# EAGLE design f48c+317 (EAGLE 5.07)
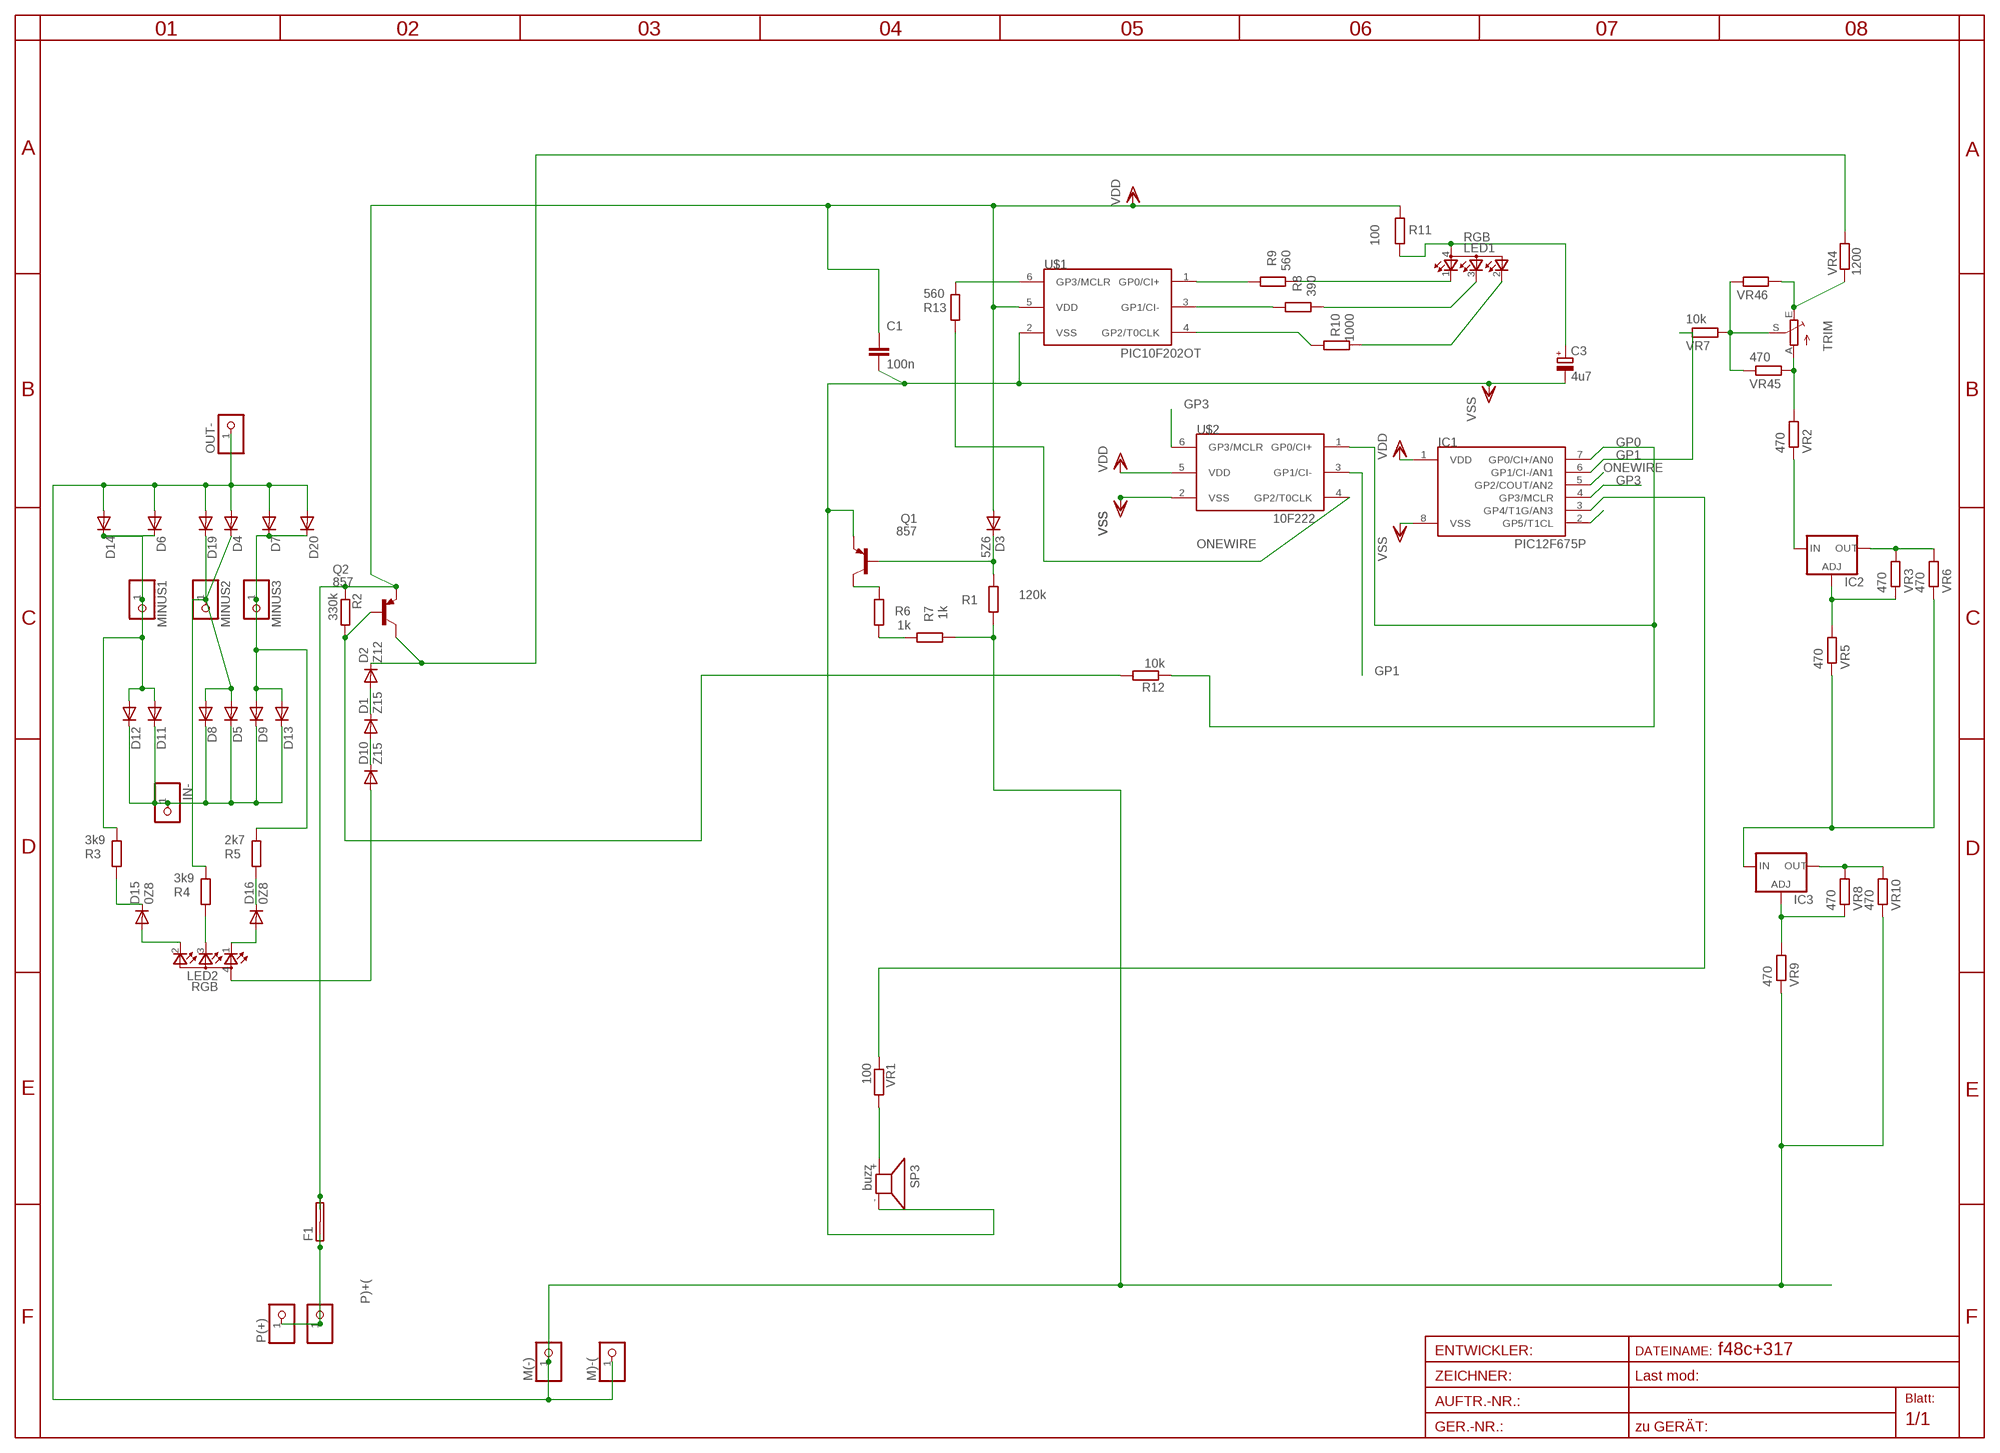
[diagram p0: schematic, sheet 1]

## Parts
C1  100n  C-EUC1206  [C1206]
C3  4u7  CPOL-EUSMCA  [SMC_A]
D1  Z15  DIODE-MINIMELF  [MINIMELF]
D2  Z12  DIODE-MINIMELF  [MINIMELF]
D3  5Z6  DIODE-MINIMELF  [MINIMELF]
D4  DIODE-SMC  [SMC]
D5  DIODE-SMC  [SMC]
D6  DIODE-SMC  [SMC]
D7  DIODE-SMC  [SMC]
D8  DIODE-SMC  [SMC]
D9  DIODE-SMC  [SMC]
D10  Z15  DIODE-MINIMELF  [MINIMELF]
D11  DIODE-SMC  [SMC]
D12  DIODE-SMC  [SMC]
D13  DIODE-SMC  [SMC]
D14  DIODE-SMC  [SMC]
D15  0Z8  DIODE-MINIMELF  [MINIMELF]
D16  0Z8  DIODE-MINIMELF  [MINIMELF]
D19  DIODE-SMC  [SMC]
D20  DIODE-SMC  [SMC]
F1  SHK20L7MM5  [7MM5]
IC1  PIC12F675P  [DIL8]
IC2  LM317LM-OUTPIN7  [SO08]
IC3  LM317LM-OUTPIN7  [SO08]
IN-  PINHD-1X12MM3  [1X2MM3]
LED1  RGB  GM1WA55311A  [FULL3528]
LED2  RGB  GM1WA55311A  [FULL3528]
M(-)  PINHD-1X14.5MM  [1X4MM5]
M)-(  PINHD-1X11X0.4  [1X01]
MINUS1  PINHD-1X12MM3  [1X2MM3]
MINUS2  PINHD-1X12MM3  [1X2MM3]
MINUS3  PINHD-1X12MM3  [1X2MM3]
OUT-  PINHD-1X12MM3  [1X2MM3]
P(+)  PINHD-1X14.5MM  [1X4MM5]
P)+(  PINHD-1X11X0.4  [1X01]
Q1  857  BC857ALT1SMD  [SOT23-BEC]
Q2  857  BC857ALT1SMD  [SOT23-BEC]
R1  120k  R-EU_R1206  [R1206]
R2  330k  R-EU_R0805  [R0805]
R3  3k9  R-EU_0207/20  [0207/20]
R4  3k9  R-EU_0207/20  [0207/20]
R5  2k7  R-EU_0207/22  [0207/22]
R6  1k  R-EU_R1206  [R1206]
R7  1k  R-EU_R1206  [R1206]
R8  390  R-EU_R0805  [R0805]
R9  560  R-EU_R0805  [R0805]
R10  1000  R-EU_R0805  [R0805]
R11  100  R-EU_R1206  [R1206]
R12  10k  R-EU_R1206  [R1206]
R13  560  R-EU_R0805  [R0805]
SP3  buzz  KSS12017MM  [KSS1202]
TRIM  TRIM_EU-S64W  [S64W]
U$1  PIC10F202OT  [SOT23-6]
U$2  10F222  PIC10F204OT  [SOT23-6]
VR1  100  R-EU_R0805  [R0805]
VR2  470  R-EU_R0805  [R0805]
VR3  470  R-EU_R0805  [R0805]
VR4  1200  R-EU_R0805  [R0805]
VR5  470  R-EU_R0805  [R0805]
VR6  470  R-EU_R0805  [R0805]
VR7  10k  R-EU_R0805  [R0805]
VR8  470  R-EU_R0805  [R0805]
VR9  470  R-EU_R0805  [R0805]
VR10  470  R-EU_R0805  [R0805]
VR45  470  R-EU_R0805  [R0805]
VR46  470  R-EU_R0805  [R0805]

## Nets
A: C3.+ LED1.4(A) R11.1
B: LED1.3(CBLUE) R8.1
B1: D6.C D11.A D12.A D14.C MINUS1.1 R3.1
B2: D7.C D9.A D13.A D20.C MINUS3.1 R5.1
B3: D4.C D5.A D8.A D19.C MINUS2.1 R4.1
BUZZ+: SP3.+ VR1.2
G: LED1.2(CGREEN) R10.1
GP0: IC1.7(GP0/CI+/AN0) R12.1 U$2.1(GP0/CI+)
GP0C: R9.2 U$1.1(GP0/CI+)
GP1: IC1.6(GP1/CI-/AN1) U$2.3(GP1/CI-) VR7.1
GP1C: R8.2 U$1.3(GP1/CI-)
GP2C: R10.2 U$1.4(GP2/T0CLK)
GP3: IC1.4(GP3/MCLR) U$2.6(GP3/MCLR)
GP3_2: R13.1 U$1.6(GP3/MCLR)
IN+: F1.1A F1.1B P(+).1 P)+(.1
IN-: D5.C D8.C D9.C D11.C D12.C D13.C IN-.1
IOBEEP: IC1.3(GP4/T1G/AN3) VR1.1
N$1: D1.C D2.A
N$2: D3.C Q1.B R1.1
N$4: D1.A D10.C
N$5: IC2.7(OUT) VR3.2 VR6.2
N$6: Q1.C R6.2
N$7: TRIM.A VR2.2 VR45.2
N$8: IC2.1(IN) VR2.1
N$9: D16.A LED2.1(CRED)
N$10: D10.A LED2.4(A)
N$11: IC2.4(ADJ) VR3.1 VR5.2
N$13: D15.C R3.2
N$14: IC3.1(IN) VR5.1 VR6.1
N$15: D15.A LED2.2(CGREEN)
N$16: LED2.3(CBLUE) R4.2
N$18: R6.1 R7.2
N$19: D16.C R5.2
N$20: Q2.B R2.2 R12.2
N$21: IC3.4(ADJ) VR8.1 VR9.2
N$22: TRIM.S VR7.2 VR45.1 VR46.1
N$24: TRIM.E VR4.1 VR46.2
N$25: D2.C Q2.C VR4.2
N$26: IC3.7(OUT) VR8.2 VR10.2
N$38: IC1.2(GP5/T1CL)
ONEWIRE: IC1.5(GP2/COUT/AN2) R13.2 U$2.4(GP2/T0CLK)
OUT-: D4.A D6.A D7.A D14.A D19.A D20.A M(-).1 M)-(.1 OUT-.1 R1.2 R7.1 VR9.1 VR10.1
R: LED1.1(CRED) R9.1
VDD: C1.1 D3.A F1.2A F1.2B IC1.1(VDD) Q2.E R2.1 R11.2 U$1.5(VDD) U$2.5(VDD)
VSS: C1.2 C3.- IC1.8(VSS) Q1.E SP3.- U$1.2(VSS) U$2.2(VSS)

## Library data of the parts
C1 = rcl:C-EU: CAPACITOR, European symbol
C3 = rcl:CPOL-EU: POLARIZED CAPACITOR, European symbol
D1-D16 D19 D20 = diode:DIODE-: DIODE
F1 = fuse:SHK20L: FUSE HOLDER 5 x 20 mm, SH contact, SHH1 Schukat, E1073 Buerklin
IC1 = microchip-3:PIC12F6*: uPC nW 1k Program Flash memory 2x Timer Comparator 10b A/D converter/ 4xIN
IC2 IC3 = v-reg-3:LM317L: Adjustable Voltage Regulator, 1.2V to 37V, 100mA
IN- M(-) M)-( MINUS1-MINUS3 OUT- P(+) P)+( = pinhead:PINHD-1X1: PIN HEADER
LED1 LED2 = led:GM1WA55311A: Chip LED RGB Source: http://document.sharpsma.com/files/GM1WA55311A_SS.pdf
Q1 Q2 = transistor-pnp:BC857*: PNP Transistror
R1-R13 VR1-VR10 VR45 VR46 = rcl-2:R-EU_: RESISTOR, European symbol
SP3 = buzzer:KSS1201: SPEAKER
TRIM = pot:TRIM_EU-: POTENTIOMETER
U$1 U$2 = microchip-3:PIC10F2*: uPC nW 0,25/0,5k Program Flash memory Comparator

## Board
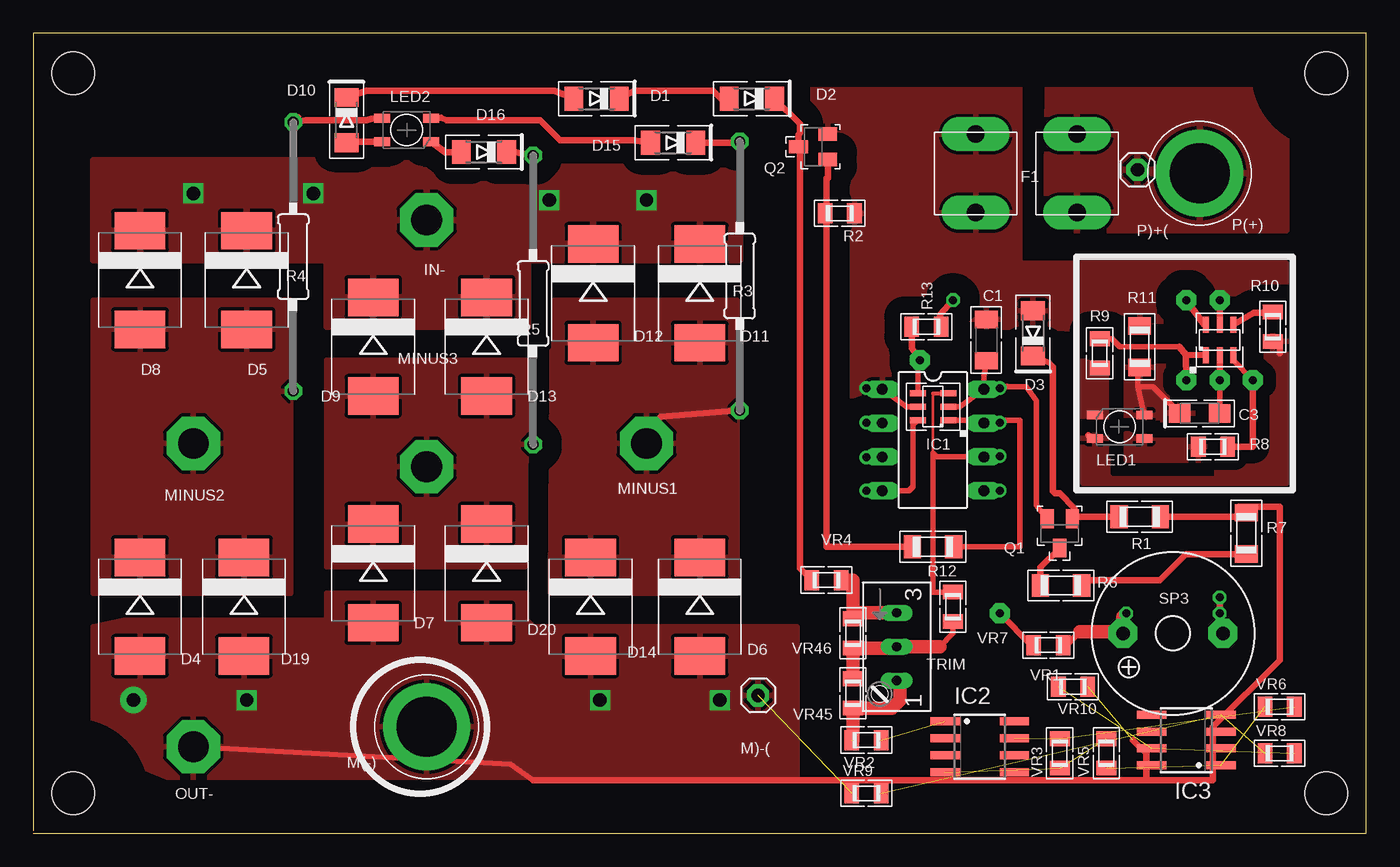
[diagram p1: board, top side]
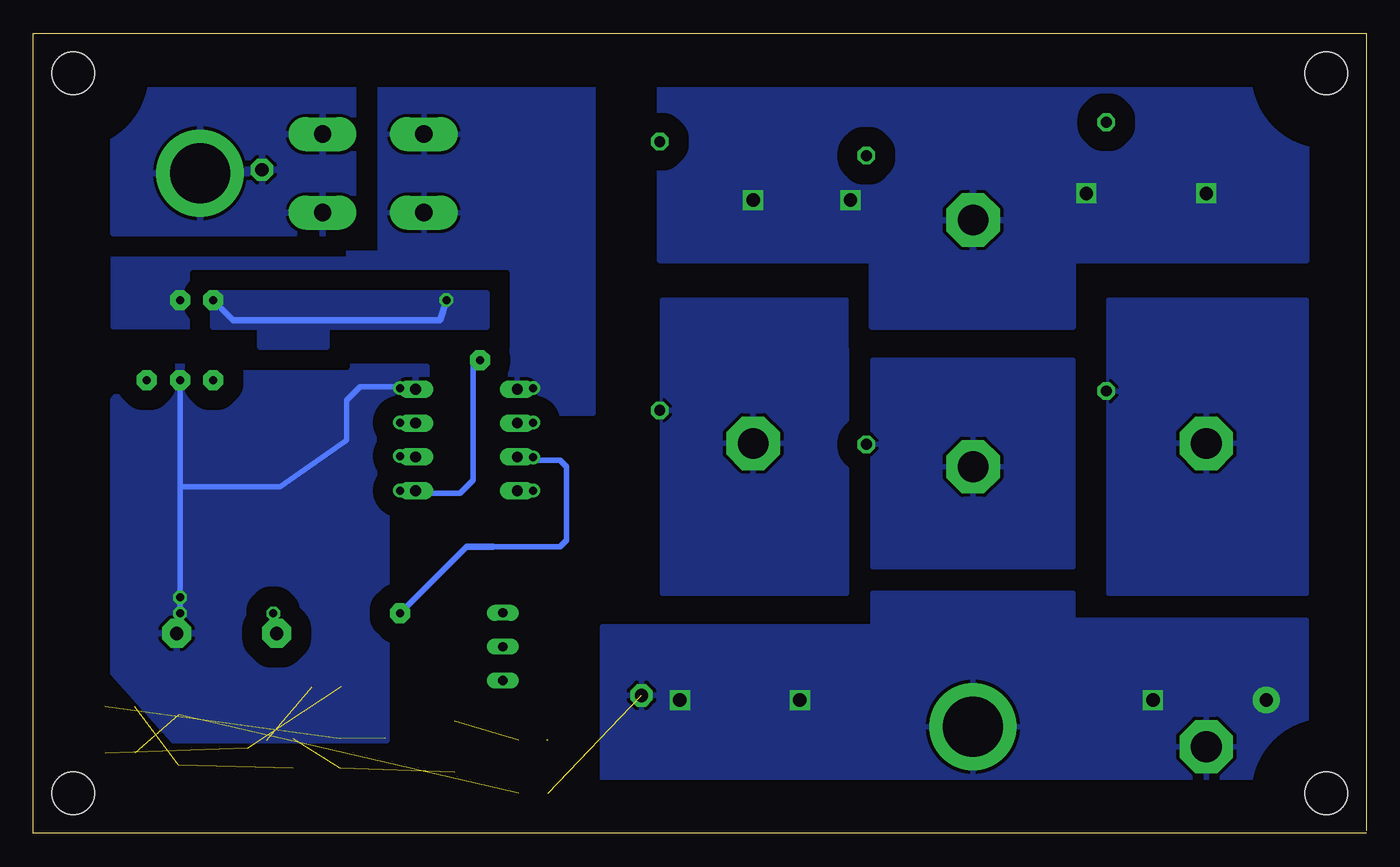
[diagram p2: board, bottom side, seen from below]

Size 100 x 60 mm. Coordinates in mm from the lower left corner, seen from the top.
Outline: 0,0 100,0 100,60 0,60 0,0.2
Copper layers (1*16): Top 0.035mm / dielectric 1.5mm / Bottom 0.035mm
Design rules "default *": minimum track width 8mil, minimum drill 4mil, track to track 8mil, track to pad 8mil, pad to pad 8mil, via to via 8mil, smd to smd 8mil, copper to edge 4mm, drill to drill 8mil, minimum pad ring 10mil, minimum via ring 8mil, stop-mask expansion 4mil, vias tented up to drill 0mil, thermal gap 10mil
Holes 3.2 mm at 3,57 3,3 97,57 97,3

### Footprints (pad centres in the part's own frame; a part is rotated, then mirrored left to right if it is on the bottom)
C1206 = smd 1.3 x 1.7: 1 -1.55,0; 2 1.55,0
SMC_A = smd 1.6 x 1.4: + -1.5,0; - 1.5,0
MINIMELF = smd 1.4 x 1.8: A 1.7,0; C -1.7,0
SMC = smd 2.8 x 3.8: A 3.7,0; C -3.7,0
7MM5 = drill 1.3 pad 2.54 long: 1A -3.8,2.94; 1B -3.8,-2.94; 2A 3.8,2.94; 2B 3.8,-2.94
DIL8 = drill 0.813 long: 1 -3.81,-3.81; 2 -1.27,-3.81; 3 1.27,-3.81; 4 3.81,-3.81; 5 3.81,3.81; 6 1.27,3.81; 7 -1.27,3.81; 8 -3.81,3.81
SO08 = smd 0.6 x 2.2: 1 -1.905,-2.6; 2 -0.635,-2.6; 3 0.635,-2.6; 4 1.905,-2.6; 5 1.905,2.6; 6 0.635,2.6; 7 -0.635,2.6; 8 -1.905,2.6
1X2MM3 = drill 2.3 pad 4 octagon: 1 0,0
FULL3528 = smd 0.65 x 1.2: 1 0.875,1.85; 2 -0.875,1.85; 3 -0.875,-1.85; 4 0.875,-1.85
1X4MM5 = drill 4.5 pad 6.35 round: 1 0,0
1X01 = drill 1 pad 1.676 octagon: 1 0,0
SOT23-BEC = smd 1 x 1.4: B -0.95,-1.1; C 0,1.1; E 0.95,-1.1
R1206 = smd 1.3 x 1.7: 1 -1.55,0; 2 1.55,0
R0805 = smd 1.1 x 1.5: 1 -1.1,0; 2 1.1,0
0207/20 = drill 0.813 octagon: 1 -10.08,0; 2 10.08,0
0207/22 = drill 0.813 octagon: 1 -10.58,0; 2 11.08,0
KSS1202 = drill 1 pad 2.159 octagon: + 3.75,0; - -3.75,0
S64W = drill 0.7 long: A 2.54,1.27; E -2.54,1.27; S 0,1.27
SOT23-6 = smd 0.45 x 1.2: 1 -1.016,-1.15; 2 0,-1.15; 3 1.016,-1.15; 4 1.016,1.15; 5 0,1.15; 6 -1.016,1.15

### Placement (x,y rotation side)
C1  71.5,37 270 top
C3  87.5,31.5 0 top
D1  42.25,55.1 180 top
D2  53.9,55.1 180 top
D3  75,37.5 90 top
D4  8,17 270 top
D5  16,41.5 270 top
D6  50,17 270 top
D7  25.5,19.5 270 top
D8  8,41.5 270 top
D9  25.5,36.5 270 top
D10  23.5,53.5 270 top
D11  50,40.5 270 top
D12  42,40.5 270 top
D13  34,36.5 270 top
D14  41.8,17 270 top
D15  48,51.8 180 top
D16  33.8,51.1 180 top
D19  15.8,17 270 top
D20  34,19.5 270 top
F1  74.5,49.5 180 top
IC1  67.5,29.5 270 top
IC2  71,6.5 270 top
IC3  86.5,7 90 top
IN-  29.5,46 180 top
LED1  81.5,30.5 90 top
LED2  28,52.75 270 top
M(-)  29.5,8 0 top
M)-(  54.37,10.35 0 top
MINUS1  46,29.25 180 top
MINUS2  12,29.25 180 top
MINUS3  29.5,27.5 180 top
OUT-  12,6.5 180 top
P(+)  87.5,49.5 0 top
P)+(  82.84,49.77 0 top
Q1  77,22.5 180 top
Q2  58.5,51.5 90 top
R1  83,23.75 0 top
R2  60.5,46.5 180 top
R3  53,41.8 90 top
R4  19.5,43.25 90 top
R5  37.5,39.75 90 top
R6  77.1,18.6 180 top
R7  91,22.5 270 top
R8  88.5,29 0 top
R9  80,36 90 top
R10  93,38 90 top
R11  83,36.5 90 top
R12  67.5,21.5 180 top
R13  67,38 180 top
SP3  85.5,15 180 top
TRIM  63.5,14 270 top
U$1  89,37 0 top
U$2  67.5,32 90 top
VR1  76.16,14.11 0 top
VR2  62.5,7 180 top
VR3  77,6 90 top
VR4  59.5,19 180 top
VR5  80.5,6 90 top
VR6  93.5,9.5 0 top
VR7  69,17 270 top
VR8  93.5,6 0 top
VR9  62.5,3 0 top
VR10  78,11 180 top
VR45  61.5,10.5 270 top
VR46  61.5,15 90 top

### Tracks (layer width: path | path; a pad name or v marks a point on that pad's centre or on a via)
A
  Top 0.4: 82.85,33.5 82.85,34.8 R11.1 | LED1.4 82.85,33.5 | C3.+ 84,33.5 82.85,33.5
  pour Top (isolate 1, rank 2): 82,35.5 87,35.5 87,31 82,31
B
  pour Top (isolate 1.016): 82,30 83.5,30 84,29.5 88,29.5 88,28 82,28
B1
  Top 0.5: R3.1 47.05,31.25 MINUS1.1
  pour Top (isolate 1.5, rank 4): 52.8,18 38.8,18 38.8,40 52.8,40
  pour Bottom (isolate 1.5, rank 4): 52.8,18 39,18 39,40 52.8,40
B2
  pour Top (isolate 1.5, rank 3): 22,20 22,35.5 37,35.5 36.9,20
  pour Bottom (isolate 1.5, rank 3): 22,20 22,35.5 37,35.5 37,20
B3
  pour Top (isolate 1.5, rank 4): 4.5,18 4.5,40 19.3,40 19.3,18
  pour Bottom (isolate 1.5, rank 4): 4.5,18 4.5,40 19.3,40 19.3,18
BUZZ+  (via drill 0.6)
  Top 0.406: 81.75,16.25 v82,16.5 81.39,15.11
  Top 0.5: VR1.2 77.5,14.11 78.5,15.11
  Top 1: 81.75,16.25 SP3.+ | 78.5,15.11 81.39,15.11
G
  Top 0.5: LED1.2 79.15,29.85 79.5,29.5 | R10.1 93.5,36.9 93.5,36
  pour Top (isolate 1, rank 2): 78.75,30 80.5,30 80.5,28 92.5,28 92.5,37.5 94,37.5 94,26.25 78.75,26.25
GP0  (via drill 0.6 pad 1)
  Top 0.4: U$2.1 71.1,30.98 IC1.7
  Top 0.406: R12.1 74,21.5 74,31 71.5,31 71.31,30.81 IC1.7 71.34,30.8 v72.5,30.8
GP0C  (via drill 0.6 pad 1.5)
  Top 0.4: R9.2 80.9,37.1 81.5,36.5 85.97,36.5
  Top 0.5: 86.48,35.88 U$1.1 | 86.48,35.88 v86.5,34 | 85.97,36.5 86.48,35.88
GP1  (via drill 0.6 pad 1)
  Top 0.2: 67.5,28.5 67.5,33
  Top 0.3: 67.5,33 68.63,33
  Top 0.4: IC1.6 67.77,28.23 67.5,28.5 67.5,18.1
  Top 0.406: 67.5,18.1 VR7.1 | IC1.6 72.43,28.23 v72.5,28.3 | 68.63,33 U$2.3
GP1C  (via drill 0.6 pad 1.5)
  Top 0.4: U$1.3 90.02,35.48 v91.5,34
  Top 0.5: v91.5,34 91.5,29 R8.2
GP2C
  Top 0.5: U$1.4 91.55,39.05 93,39.05 R10.2
GP3  (via drill 0.6 pad 1)
  Top 0.4: IC1.4 65.69,25.69 66,26 66,30.63 U$2.6
  Top 0.406: IC1.4 v62.51,25.69 v62.5,25.7
GP3_2  (via drill 0.6 pad 1, 0.6 pad 1.5)
  Top 0.5: U$1.6 87.85,38.15 v86.5,40 | v69,40 68,38.9 R13.1
  Bottom 0.5: v86.5,40 85,38.5 69.5,38.5 v69,40
  pour Bottom (isolate 1): 66,40.5 86.5,40.5 86.5,38 83,38 83,36.5 78,36.5 78,38 66,38
IN+
  pour Top (isolate 1.5): 76.1,56 94,56 94,45.25 77,45.25 76,46
  pour Bottom (isolate 1.5): 76,56 94,56 94,45 77,45 76,46
IN-  (via drill 1 pad 1)
  other vias: 12,48 21,48 38.7,47.5 46,47.5
  pour Top (isolate 1.5): 4.5,50.5 53,50.5 53,43 37.1,43 37.1,38 22,38 22,43 4.5,43
  pour Bottom (isolate 1.5): 4.5,56 53,56 53,43 37.1,43 37.1,38 22,38 22,43 4.5,43
IOBEEP  (via drill 0.6 pad 1, 0.6 pad 1.5)
  Top 0.406: v62.5,28.2 62.7,28
  Top 0.5: VR1.1 74.89,14.11 v72.5,16.5
  Bottom 0.406: v72.5,16.5 72,16.5 | 65.5,21.5 60.5,21.5 60,22 60,27.5 60.5,28 63.46,28 IC1.3
  Bottom 0.5: 63.46,28 62.5,28 v62.5,28.2 | 65.5,21.5 67.5,21.5 v72.5,16.5
N$1
  Top 0.5: D2.A 51.6,55.1 51,55.7 45.1,55.7 D1.C
N$2
  Top 0.406: D3.C 76.22,35.28 76.5,35
  Top 0.5: 76.5,35 76.5,25.65 76.65,25.5 77,25.5 78.1,24.4 78.1,23.75 | 78.1,23.75 R1.1 | Q1.B 78.1,23.75
N$3  (via drill 0.6 pad 1)
  other vias: 72.5,25.7
N$4
  Top 0.5: D10.C 25,55.7 39.1,55.7 D1.A
N$5  (2 unrouted)
N$6
  Top 0.5: R6.2 75.55,19.95 Q1.C
N$7  (1 unrouted)
  Top 0.406: 65,11.23 TRIM.A
  Top 1: 65,11.23 65,10 64.4,9.4 VR45.2 61.5,7
N$8  (1 unrouted)
N$9
  Top 0.5: D16.A 30.88,51.1 LED2.1
N$10
  Top 0.5: LED2.4 23.68,51.88 D10.A
N$11  (2 unrouted)
N$13
  Top 0.5: D15.C 53,51.8 R3.2
N$14  (2 unrouted)
N$15
  Top 0.5: LED2.2 30.6,53.67 31,53.5 36.62,53.48 38.02,53.48 39.5,52 45,52 D15.A
N$16
  Top 0.5: LED2.3 25.38,53.58 25,53.5 20.47,53.5 R4.2 19.87,53.7
N$18
  Top 0.5: R7.2 86.45,20.95 84.5,19 79.05,19 R6.1
N$19
  Top 0.5: D16.C 36.18,51.1 R5.2
N$20
  Top 0.5: R12.2 59.5,21.5 59.5,45 59.5,46.5 R2.2 59.4,47 59.5,47 59.5,49.13 59.6,49.13 Q2.B
N$21  (2 unrouted)
N$22
  Top 0.406: 64.67,13.9 TRIM.S | 68,14 69,15 VR7.2
  Top 1: VR45.1 VR46.1 64.67,13.9 | TRIM.S 68,14
N$24
  Top 0.406: VR46.2 61.94,16.54
  Top 1: 61.94,16.54 TRIM.E | VR46.2 61.5,19 VR4.1
N$25
  Top 0.406: 57.4,52.4 57.5,52.5
  Top 0.5: D2.C 57.5,53.2 57.5,52.5 | 57.4,52.4 Q2.C 57.5,51.5 57.5,19.9 VR4.2
N$26  (2 unrouted)
N$29  (via drill 0.6 pad 1)
  other vias: 62.5,30.8
ONEWIRE  (via drill 0.6 pad 1.5)
  Top 0.4: U$2.4 66.35,34.5 66.35,34.85
  Top 0.406: v66.5,35.5 66.35,35.85 66.35,34.5
  Top 0.5: R13.2 65.9,36.4 v66.5,35.5
  Bottom 0.406: v66.5,35.5 67,35.5 67,26.5 68,25.5 71.12,25.5 IC1.5
OUT-  (via drill 1 pad 1, 1 pad 2)  (2 unrouted)
  Top 0.406: 90.45,24.5 R7.1 91,23.75 | 37.5,4 35.8,5.2 OUT-.1
  Top 0.5: 90.45,24.5 93.5,24.5 93.5,13 88.5,8 88.5,4 83.5,4 | 37.5,4 83.5,4 | 82.5,7 83.5,6 83.5,4 | 91,23.75 R1.2
  other vias: 51.5,10 42.5,10 16,10 7.5,10
  pour Top (isolate 1.422, rank 4): 57.3,4 11.8,3.5 4.5,6.5 4.5,15.5 6.8,16 22,16 22,18 37,18 37,16 37.5,15.5 57.3,15.5
  pour Bottom (isolate 1.422, rank 4): 57.3,4 8.3,3.5 4.5,6.5 4.5,16 22,16 22,18 37,18 37,15.5 57.3,15.5
R
  pour Top (isolate 1, rank 3, no thermals): 78.75,35.5 80.5,35.5 80.5,31 78.75,31
VDD  (via drill 0.6 pad 1, 0.6 pad 1.5)
  Top 0.4: U$2.5 65.5,32 IC1.1 63.5,33.5
  Top 0.406: 63.5,33.5 62.6,33.5 v62.5,33.4
  Top 0.5: U$1.5 v89,40
  pour Top (isolate 1.5, rank 2): 74,42.75 74,56 58.5,56 58.5,23.5 64,23.5 64,26 64.5,33.5 65,34 69,38.5 70,38 94,37.5 94,42.75
  pour Bottom (isolate 1.5, rank 2): 74,43.5 74,56 58,56 58,31.5 64.5,31.5 64.5,33.5 65,34 69,38.5 70,38 94,38 94,43.5
VSS  (via drill 0.6, 0.6 pad 1, 0.6 pad 1.5)
  Top 0.4: v89,34 C3.- | 69.5,32 U$2.2
  Top 0.406: SP3.- 89.25,15.75 v89,16.5 | IC1.8 73.05,33.55 | IC1.8 69.5,32 | Q1.E 75.25,24.6 75.25,32.45 74.5,33.5 73,33.5 | 73,33.5 IC1.8 | C1.2 71.31,34.26 IC1.8 | 73,33.5 72.6,33.5 v72.5,33.4
  Top 0.5: v89,34 U$1.2 | v89,16.5 v89,17.7
  Bottom 0.406: 89,26 v89,16.5 | 89,26 v89,34 | 89,26 81.5,26 76.5,29.5 76.5,32.5 75.5,33.5 73,33.5 IC1.8
  pour Bottom (isolate 1.5, rank 3): 70.5,35 92,35 94,32.5 94,12 89.5,7 73.5,7 73.5,30.5 71,30.5 70.5,31

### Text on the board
tTest: 4v4
Document: 1m | 10u | 10u | 300u | 2mA | 500u | 1m | 2m | 300u | 300u | 30u | 5m | 14m | 12m | 500u | 5m | 5m | 5m | 5m | 5m | 5m | 40m | 40m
